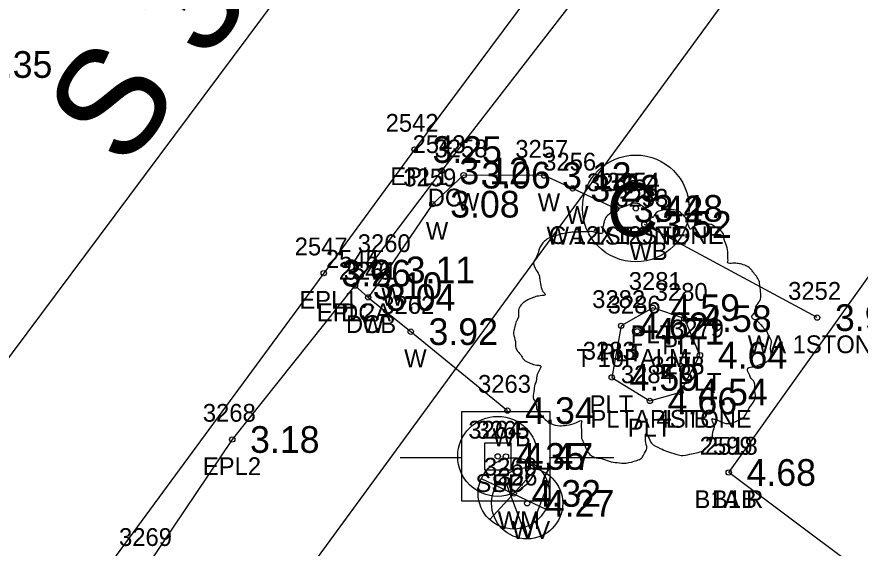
# Model space of a CAD drawing. Extents: x 2608598 to 2610682, y 641451 to 643526.
# Drawn here: x 2610013.59 to 2610060.97, y 642007.4 to 642037.25 of the extents above; entities that cross this region are included whole.
import ezdxf

# ---------------------------------------------------------------- set-up
doc = ezdxf.new("R2010")
doc.units = 0
for name, color, linetype in [('RD_EX_Bldg', 7, 'Continuous'), ('RD_EX_Bldg_txCode', 7, 'Continuous'), ('RD_EX_BldgApp', 7, 'Continuous'), ('RD_EX_BldgApp_txCode', 7, 'Continuous'), ('RD_EX_Conc', 7, 'Continuous'), ('RD_EX_Conc_txCode', 7, 'Continuous'), ('RD_EX_DR_Pipe', 7, 'Continuous'), ('RD_EX_Misc_txCode', 7, 'Continuous'), ('RD_EX_Road', 7, 'Continuous'), ('RD_EX_Road_txCode', 7, 'Continuous'), ('RD_EX_TX_Bldg_ELEV', 7, 'Continuous'), ('RD_EX_TX_BldgApp_ELEV', 7, 'Continuous'), ('RD_EX_TX_Conc_ELEV', 7, 'Continuous'), ('RD_EX_TX_Misc_ELEV', 7, 'Continuous'), ('RD_EX_TX_Road_ELEV', 7, 'Continuous'), ('RD_EX_TX_UT_ELEV', 7, 'Continuous'), ('RD_EX_TX_VEG_ELEV', 7, 'Continuous'), ('RD_EX_UT', 7, 'Continuous'), ('RD_EX_UT_txCode', 7, 'Continuous'), ('RD_EX_VEG', 7, 'Continuous'), ('RD_EX_VEG_txCode', 7, 'Continuous'), ('RD_HC_Cl', 7, 'Continuous'), ('RD_HC_Data', 7, 'Continuous'), ('RD_HC_Survey_ELEV', 7, 'Continuous'), ('RD_SMD_Locator', 7, 'Continuous')]:
    doc.layers.add(name, color=color, linetype=linetype)

msp = doc.modelspace()

# ---------------------------------------------------------------- linework, layer by layer
at = {"layer": 'RD_EX_Bldg'}
msp.add_lwpolyline([(2610053.59, 642011.651), (2610094.327, 642068.736), (2610111.856, 642055.619), (2610105.498, 642045.99), (2610112.03, 642040.97), (2610078.047, 641993.35), (2610053.59, 642011.651)], dxfattribs=at)
at = {"layer": 'RD_EX_BldgApp'}
msp.add_line((2610058.557, 642020.354), (2610048.849, 642025.584), dxfattribs=at)
for points in [[(2610047.256, 642026.455), (2610044.819, 642027.615), (2610043.225, 642028.33), (2610038.689, 642028.357), (2610036.938, 642026.725), (2610034.437, 642023.032), (2610033.33, 642021.486), (2610035.723, 642019.563), (2610041.157, 642015.128)], [(2610050.879, 642016.167), (2610051.974, 642018.242), (2610051.098, 642020.297), (2610049.32, 642020.91), (2610047.547, 642019.891), (2610047.018, 642016.991), (2610049.159, 642015.668), (2610050.879, 642016.167)]]:
    msp.add_lwpolyline(points, dxfattribs=at)
msp.add_circle((2610048.368, 642026.488), 3, dxfattribs=at)
at = {"layer": 'RD_EX_Conc'}
msp.add_lwpolyline([(2610062.865, 642060.944), (2610060.494, 642059.714), (2610051.415, 642046.652), (2610037.455, 642028.596), (2610032.589, 642022.148), (2610033.33, 642021.486)], dxfattribs=at)
at = {"layer": 'RD_EX_DR_Pipe'}
msp.add_line((2610073.519, 642065.711), (2609997.656, 641962.025), dxfattribs=at)
at = {"layer": 'RD_EX_Road'}
for points in [[(2610116.512, 642103.007), (2610109.419, 642106.335), (2610102.937, 642107.104), (2610095.974, 642105.732), (2610091.028, 642103.088), (2610067.446, 642071.713), (2610058.11, 642059.075), (2610043.044, 642039.371), (2610035.942, 642029.795), (2610030.832, 642022.851), (2609999.348, 641980.077), (2609984.87, 641960.622)], [(2610032.589, 642022.148), (2610025.693, 642013.504), (2610020.985, 642006.523), (2610018.112, 642001.928), (2610002.773, 641980.423), (2610001.184, 641979.118), (2609987.485, 641958.197)]]:
    msp.add_lwpolyline(points, dxfattribs=at)
at = {"layer": 'RD_EX_UT'}
for p, q in [((2610043.565, 642015.058), (2610038.565, 642015.058)), ((2610038.565, 642015.058), (2610038.565, 642010.058)), ((2610043.565, 642010.058), (2610043.565, 642015.058)), ((2610041.362, 642013.305), (2610039.861, 642013.305)), ((2610039.861, 642013.305), (2610039.861, 642011.805)), ((2610041.361, 642011.805), (2610041.362, 642013.305)), ((2610035.134, 642012.495), (2610038.603, 642012.495)), ((2610043.494, 642012.495), (2610047.134, 642012.495)), ((2610039.861, 642011.805), (2610041.361, 642011.805)), ((2610040.157, 642009.018), (2610042.825, 642011.914)), ((2610039.676, 642011.313), (2610043.307, 642009.6)), ((2610042.262, 642007.927), (2610040.958, 642011.409)), ((2610042.262, 642007.927), (2610043.584, 642011.372)), ((2610038.565, 642010.058), (2610043.565, 642010.058))]:
    msp.add_line(p, q, dxfattribs=at)
for centre, radius in [((2610040.611, 642012.555), 2.25), ((2610041.509, 642010.476), 2), ((2610042.262, 642009.919), 2)]:
    msp.add_circle(centre, radius, dxfattribs=at)
at = {"layer": 'RD_EX_VEG'}
for centre, radius in [((2610048.44, 642019.583), 0.25), ((2610048.427, 642019.564), 0.0001)]:
    msp.add_circle(centre, radius, dxfattribs=at)
for points in [[(2610048.572, 642026.75), (2610048.272, 642026.775), (2610047.947, 642026.675), (2610047.697, 642026.575), (2610047.472, 642026.5), (2610047.247, 642026.4), (2610046.947, 642026.225), (2610046.722, 642026.025), (2610046.597, 642025.775), (2610046.547, 642025.55), (2610046.498, 642025.276), (2610046.498, 642025.101), (2610046.373, 642025.076), (2610046.223, 642025.101), (2610045.973, 642025.176), (2610045.723, 642025.176), (2610045.473, 642025.176), (2610045.123, 642025.151), (2610044.773, 642025.151), (2610044.498, 642025.101), (2610044.174, 642025.051), (2610043.799, 642024.926), (2610043.449, 642024.801), (2610043.149, 642024.551), (2610042.899, 642024.076), (2610042.774, 642023.726), (2610042.624, 642023.476), (2610042.774, 642023.027), (2610042.949, 642022.677), (2610042.974, 642022.477), (2610043.049, 642022.052), (2610043.149, 642021.827), (2610043.274, 642021.627), (2610043.199, 642021.602), (2610042.824, 642021.552), (2610042.524, 642021.452), (2610042.099, 642021.227), (2610041.875, 642021.002), (2610041.775, 642020.677), (2610041.75, 642020.328), (2610041.65, 642020.128), (2610041.575, 642019.853), (2610041.55, 642019.778), (2610041.5, 642019.453), (2610041.6, 642019.003), (2610041.625, 642018.653), (2610041.75, 642018.428), (2610041.9, 642018.254), (2610042.074, 642018.004), (2610042.474, 642017.779), (2610042.799, 642017.679), (2610042.999, 642017.654), (2610042.824, 642017.154), (2610042.774, 642016.804), (2610042.649, 642016.404), (2610042.649, 642016.329), (2610042.599, 642015.855), (2610042.749, 642015.53), (2610042.824, 642015.155), (2610042.999, 642014.93), (2610043.274, 642014.63), (2610043.599, 642014.405), (2610044.099, 642014.28), (2610044.498, 642014.305), (2610045.073, 642014.48), (2610045.323, 642014.555), (2610045.298, 642014.38), (2610045.323, 642014.005), (2610045.323, 642013.581), (2610045.473, 642013.256), (2610045.573, 642012.981), (2610045.723, 642012.731), (2610046.048, 642012.506), (2610046.448, 642012.431), (2610046.872, 642012.281), (2610047.322, 642012.206), (2610047.822, 642012.181), (2610048.422, 642012.331), (2610048.697, 642012.456), (2610048.797, 642012.631), (2610048.996, 642013.006), (2610048.946, 642013.231), (2610048.971, 642013.831), (2610049.071, 642013.656), (2610049.246, 642013.306), (2610049.746, 642013.006), (2610050.146, 642012.831), (2610050.621, 642012.681), (2610050.921, 642012.606), (2610051.395, 642012.681), (2610051.77, 642012.756), (2610052.145, 642012.881), (2610052.445, 642013.156), (2610052.62, 642013.431), (2610052.67, 642013.706), (2610052.745, 642014.08), (2610052.795, 642014.255)], [(2610052.795, 642014.255), (2610052.72, 642014.43), (2610052.67, 642014.68), (2610052.745, 642014.655), (2610052.92, 642014.605), (2610053.195, 642014.48), (2610053.42, 642014.405), (2610053.744, 642014.43), (2610054.019, 642014.53), (2610054.469, 642014.805), (2610054.744, 642015.28), (2610055.019, 642015.68), (2610055.094, 642016.005), (2610055.044, 642016.229), (2610055.019, 642016.729), (2610054.819, 642016.979), (2610054.769, 642017.104), (2610054.669, 642017.504), (2610054.744, 642017.554), (2610055.019, 642017.604), (2610055.394, 642017.729), (2610055.669, 642017.854), (2610055.893, 642018.029), (2610055.968, 642018.254), (2610055.943, 642018.653), (2610055.993, 642019.053), (2610055.918, 642019.203), (2610055.818, 642019.353), (2610055.743, 642019.553), (2610055.594, 642019.703), (2610055.494, 642019.853), (2610055.394, 642019.953), (2610055.269, 642020.103), (2610055.094, 642020.228), (2610054.944, 642020.278), (2610054.894, 642020.428), (2610055.044, 642020.628), (2610055.094, 642020.727), (2610055.119, 642020.952), (2610055.344, 642021.302), (2610055.394, 642021.702), (2610055.344, 642022.127), (2610055.294, 642022.402), (2610055.144, 642022.677), (2610054.944, 642022.927), (2610054.819, 642023.101), (2610054.644, 642023.226), (2610054.319, 642023.351), (2610054.069, 642023.401), (2610053.719, 642023.401), (2610053.519, 642023.451), (2610053.544, 642023.501), (2610053.544, 642023.651), (2610053.544, 642023.926), (2610053.469, 642024.376), (2610053.32, 642024.876), (2610053.32, 642024.901), (2610053.22, 642025.151), (2610052.995, 642025.35), (2610052.82, 642025.45), (2610052.62, 642025.575), (2610052.37, 642025.6), (2610052.07, 642025.6), (2610051.795, 642025.55), (2610051.595, 642025.45), (2610051.42, 642025.325), (2610051.345, 642025.475), (2610051.245, 642025.775), (2610051.195, 642025.925), (2610051.046, 642026.1), (2610050.821, 642026.3), (2610050.371, 642026.425), (2610049.746, 642026.35), (2610049.446, 642026.15), (2610049.296, 642025.975), (2610049.246, 642026.1), (2610049.046, 642026.3), (2610048.946, 642026.475), (2610048.772, 642026.6), (2610048.622, 642026.7), (2610048.522, 642026.75)]]:
    msp.add_spline(points, degree=3, dxfattribs=at)
at = {"layer": 'RD_HC_Cl'}
msp.add_line((2610099.475, 642133.968), (2609975.324, 641967.39), dxfattribs=at)
at = {"layer": 'RD_SMD_Locator'}
for centre in [(2610035.942, 642029.795), (2610037.455, 642028.596), (2610038.689, 642028.357), (2610043.225, 642028.33), (2610044.819, 642027.615), (2610036.938, 642026.725), (2610047.256, 642026.455), (2610048.368, 642026.488), (2610048.849, 642025.584), (2610034.437, 642023.032), (2610030.832, 642022.851), (2610032.589, 642022.148), (2610032.589, 642022.148), (2610033.33, 642021.486), (2610033.33, 642021.486), (2610049.32, 642020.91), (2610051.098, 642020.297), (2610058.557, 642020.354), (2610047.547, 642019.891), (2610035.723, 642019.563), (2610048.44, 642019.583), (2610051.974, 642018.242), (2610047.018, 642016.991), (2610050.879, 642016.167), (2610050.879, 642016.167), (2610049.159, 642015.668), (2610041.157, 642015.128), (2610025.693, 642013.504), (2610040.611, 642012.555), (2610041.074, 642012.549), (2610053.59, 642011.651), (2610053.59, 642011.651), (2610041.509, 642010.476), (2610042.262, 642009.919)]:
    msp.add_circle(centre, 0.15, dxfattribs=at)

# ---------------------------------------------------------------- texts
at = {"layer": 'RD_EX_Bldg_txCode'}
for s, p in [('2599', (2610051.96, 642012.651)), ('2518', (2610052.244, 642012.651)), ('B1A R', (2610051.669, 642009.651)), ('B1B', (2610052.645, 642009.651))]:
    msp.add_text(s, height=1, dxfattribs=at).set_placement(p)
at = {"layer": 'RD_EX_BldgApp'}
msp.add_text('C', height=3, dxfattribs=at).set_placement((2610046.737, 642024.926))
at = {"layer": 'RD_EX_BldgApp_txCode'}
for s, p in [('3254', (2610046.738, 642027.488)), ('C 12X12STONE', (2610043.49, 642024.488)), ('3281', (2610047.974, 642021.91)), ('3280', (2610049.429, 642021.297)), ('3282', (2610045.917, 642020.891)), ('3279', (2610050.344, 642019.242)), ('PLT', (2610048.076, 642018.91)), ('PLT', (2610049.854, 642018.297)), ('3283', (2610045.388, 642017.991)), ('PLT', (2610046.303, 642017.891)), ('3278', (2610049.249, 642017.167)), ('3285', (2610049.249, 642017.167)), ('3284', (2610047.529, 642016.668)), ('PLT', (2610050.73, 642016.242)), ('PLT', (2610045.774, 642014.991)), ('PLTA 4STONE', (2610045.82, 642014.167)), ('PLTB', (2610049.162, 642014.167)), ('PLT', (2610047.915, 642013.668))]:
    msp.add_text(s, height=1, dxfattribs=at).set_placement(p)
at = {"layer": 'RD_EX_Conc_txCode'}
for s, p in [('2543', (2610035.825, 642029.596)), ('DC', (2610036.675, 642026.596)), ('2544', (2610030.959, 642023.148)), ('2546', (2610031.677, 642022.486)), ('DC', (2610031.809, 642020.148)), ('DCB', (2610032.078, 642019.486))]:
    msp.add_text(s, height=1, dxfattribs=at).set_placement(p)
at = {"layer": 'RD_EX_Misc_txCode'}
for s, p in [('3258', (2610037.059, 642029.357)), ('3257', (2610041.595, 642029.33)), ('3256', (2610043.165, 642028.615)), ('3259', (2610035.308, 642027.725)), ('3255', (2610045.626, 642027.455)), ('W', (2610038.319, 642026.357)), ('3253', (2610047.219, 642026.584)), ('W', (2610042.855, 642026.33)), ('W', (2610044.449, 642025.615)), ('W', (2610036.568, 642024.725)), ('WA 1STONE', (2610043.355, 642024.455)), ('3260', (2610032.744, 642024.032)), ('WB', (2610048.007, 642023.584)), ('3261', (2610031.96, 642022.486)), ('3252', (2610056.927, 642021.354)), ('W', (2610034.067, 642021.032)), ('3262', (2610034.069, 642020.563)), ('W', (2610032.96, 642019.486)), ('WA 1STONE', (2610054.655, 642018.354)), ('W', (2610035.353, 642017.563)), ('3263', (2610039.503, 642016.128)), ('WB', (2610040.314, 642013.128))]:
    msp.add_text(s, height=1, dxfattribs=at).set_placement(p)
at = {"layer": 'RD_EX_Road_txCode'}
for s, p in [('2542', (2610034.312, 642030.795)), ('EPL1', (2610034.572, 642027.795)), ('2547', (2610029.202, 642023.851)), ('2545', (2610030.959, 642023.148)), ('EPL1', (2610029.462, 642020.851)), ('EPL2A', (2610030.447, 642020.148)), ('3268', (2610024.04, 642014.504)), ('EPL2', (2610024.04, 642011.504)), ('3269', (2610019.331, 642007.523))]:
    msp.add_text(s, height=1, dxfattribs=at).set_placement(p)
at = {"layer": 'RD_EX_TX_Bldg_ELEV'}
msp.add_text('4.68', height=1.5, dxfattribs=at).set_placement((2610054.59, 642010.901))
msp.add_text('4.68', height=1.5, dxfattribs=at).set_placement((2610054.59, 642010.901))
at = {"layer": 'RD_EX_TX_BldgApp_ELEV'}
for s, p in [('3.48', (2610049.368, 642025.738)), ('4.59', (2610050.32, 642020.16)), ('4.58', (2610052.098, 642019.547)), ('4.62', (2610048.547, 642019.141)), ('4.64', (2610052.974, 642017.492)), ('4.59', (2610048.018, 642016.241)), ('4.54', (2610051.879, 642015.417)), ('4.54', (2610051.879, 642015.417)), ('4.66', (2610050.159, 642014.918))]:
    msp.add_text(s, height=1.5, dxfattribs=at).set_placement(p)
at = {"layer": 'RD_EX_TX_Conc_ELEV'}
for s, p in [('3.12', (2610038.455, 642027.846)), ('3.10', (2610033.589, 642021.398)), ('3.04', (2610034.33, 642020.736))]:
    msp.add_text(s, height=1.5, dxfattribs=at).set_placement(p)
at = {"layer": 'RD_EX_TX_Misc_ELEV'}
for s, p in [('3.06', (2610039.689, 642027.607)), ('3.12', (2610044.225, 642027.58)), ('3.23', (2610045.819, 642026.865)), ('3.08', (2610037.938, 642025.975)), ('3.42', (2610048.256, 642025.705)), ('3.52', (2610049.849, 642024.834)), ('3.11', (2610035.437, 642022.282)), ('3.04', (2610034.33, 642020.736)), ('3.96', (2610059.557, 642019.604)), ('3.92', (2610036.723, 642018.813)), ('4.34', (2610042.157, 642014.378))]:
    msp.add_text(s, height=1.5, dxfattribs=at).set_placement(p)
at = {"layer": 'RD_EX_TX_Road_ELEV'}
for s, p in [('3.35', (2610011.682, 642033.822)), ('3.25', (2610036.942, 642029.045)), ('3.26', (2610031.832, 642022.101)), ('3.10', (2610033.589, 642021.398)), ('3.18', (2610026.693, 642012.754))]:
    msp.add_text(s, height=1.5, dxfattribs=at).set_placement(p)
at = {"layer": 'RD_EX_TX_UT_ELEV'}
for s, p in [('4.35', (2610041.611, 642011.805)), ('4.32', (2610042.509, 642009.726)), ('4.27', (2610043.262, 642009.169))]:
    msp.add_text(s, height=1.5, dxfattribs=at).set_placement(p)
at = {"layer": 'RD_EX_TX_VEG_ELEV'}
msp.add_text('4.71', height=1.5, dxfattribs=at).set_placement((2610049.44, 642018.833))
at = {"layer": 'RD_EX_UT_txCode'}
for s, p in [('3264', (2610038.958, 642013.555)), ('3265', (2610039.421, 642013.549)), ('3266', (2610039.832, 642011.476)), ('3267', (2610040.609, 642010.919)), ('SSC', (2610039.359, 642010.555)), ('PP', (2610040.295, 642010.549)), ('WM', (2610040.604, 642008.476)), ('WV', (2610041.404, 642007.919))]:
    msp.add_text(s, height=1, dxfattribs=at).set_placement(p)
at = {"layer": 'RD_EX_VEG_txCode'}
for s, p in [('3286', (2610046.786, 642020.583)), ('T 10PALM', (2610045.03, 642017.583))]:
    msp.add_text(s, height=1, dxfattribs=at).set_placement(p)
at = {"layer": 'RD_HC_Data'}
msp.add_text('S 36%%d 41\' 50" W', height=6, rotation=53.3029, dxfattribs=at).set_placement((2610019.672, 642028.568))
at = {"layer": 'RD_HC_Survey_ELEV'}
msp.add_text('4.47', height=1.5, dxfattribs=at).set_placement((2610042.074, 642011.799))

doc.saveas('drawing.dxf')
